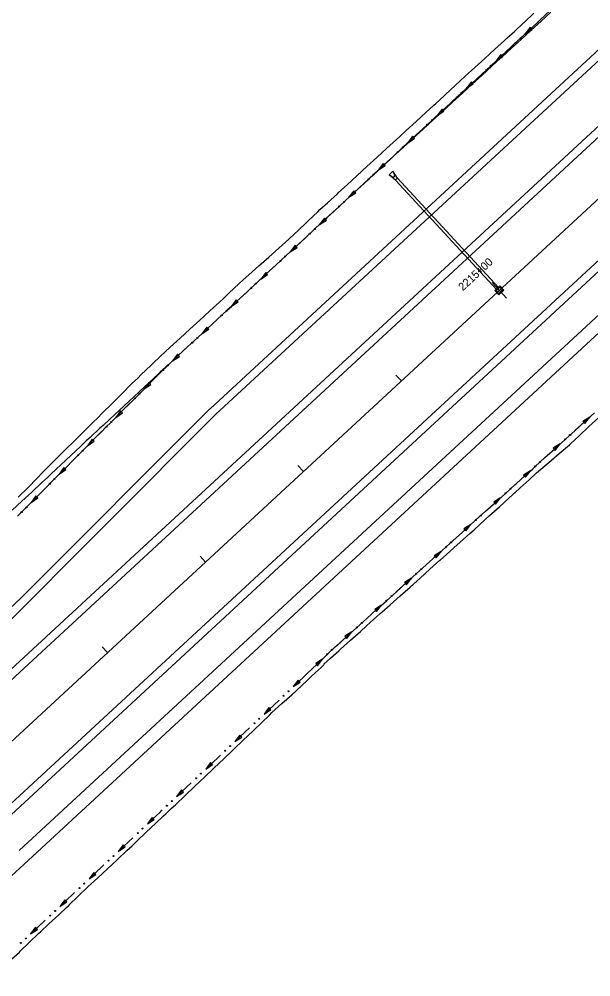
# Model space of a CAD drawing. Extents: x 1611108 to 1749517, y 619561 to 797725.
# Drawn here: x 1726166 to 1726595, y 770332 to 771050 of the extents above; entities that cross this region are included whole.
import ezdxf

# ---------------------------------------------------------------- set-up
doc = ezdxf.new("R2010")
doc.units = 0
for name, color, linetype in [('R_Ditch', 7, 'Continuous'), ('R_Drainage', 7, 'Continuous'), ('R_Horz Alg', 7, 'Continuous'), ('R_Horz Alg Stationing', 7, 'Continuous'), ('R_Proposed Const Limits', 7, 'Continuous'), ('R_Proposed Road', 7, 'Continuous')]:
    doc.layers.add(name, color=color, linetype=linetype)

msp = doc.modelspace()

# ---------------------------------------------------------------- linework, layer by layer
at = {"layer": 'R_Ditch'}
for p, q in [((1726549.3, 771043.7), (1726545.62, 771038.85)), ((1726545.62, 771038.85), (1726550.74, 771042.15)), ((1726550.74, 771042.15), (1726549.3, 771043.7)), ((1726527.27, 771023.28), (1726523.59, 771018.42)), ((1726523.59, 771018.42), (1726528.71, 771021.73)), ((1726528.71, 771021.73), (1726527.27, 771023.28)), ((1726505.24, 771002.85), (1726501.56, 770998)), ((1726501.56, 770998), (1726506.68, 771001.3)), ((1726506.68, 771001.3), (1726505.24, 771002.85)), ((1726483.22, 770982.43), (1726479.54, 770977.58)), ((1726484.65, 770980.88), (1726483.22, 770982.43)), ((1726479.54, 770977.58), (1726484.65, 770980.88)), ((1726461.19, 770962.01), (1726457.51, 770957.15)), ((1726462.63, 770960.46), (1726461.19, 770962.01)), ((1726457.51, 770957.15), (1726462.63, 770960.46)), ((1726439.16, 770941.59), (1726435.48, 770936.73)), ((1726435.48, 770936.73), (1726440.6, 770940.03)), ((1726440.6, 770940.03), (1726439.16, 770941.59)), ((1726417.13, 770921.16), (1726413.45, 770916.31)), ((1726413.45, 770916.31), (1726418.57, 770919.61)), ((1726418.57, 770919.61), (1726417.13, 770921.16)), ((1726395.11, 770900.74), (1726391.43, 770895.89)), ((1726391.43, 770895.89), (1726396.55, 770899.19)), ((1726396.55, 770899.19), (1726395.11, 770900.74)), ((1726373.08, 770880.32), (1726369.4, 770875.46)), ((1726369.4, 770875.46), (1726374.52, 770878.77)), ((1726374.52, 770878.77), (1726373.08, 770880.32)), ((1726351.05, 770859.89), (1726347.37, 770855.04)), ((1726347.37, 770855.04), (1726352.49, 770858.34)), ((1726352.49, 770858.34), (1726351.05, 770859.89)), ((1726329.03, 770839.47), (1726325.35, 770834.62)), ((1726330.47, 770837.92), (1726329.03, 770839.47)), ((1726325.35, 770834.62), (1726330.47, 770837.92)), ((1726307, 770819.05), (1726303.32, 770814.19)), ((1726303.32, 770814.19), (1726308.44, 770817.5)), ((1726308.44, 770817.5), (1726307, 770819.05)), ((1726284.97, 770798.63), (1726281.3, 770793.76)), ((1726281.3, 770793.76), (1726286.41, 770797.08)), ((1726286.41, 770797.08), (1726284.97, 770798.63)), ((1726263.44, 770777.63), (1726259.95, 770772.64)), ((1726259.95, 770772.64), (1726264.94, 770776.13)), ((1726264.94, 770776.13), (1726263.44, 770777.63)), ((1726242.2, 770756.39), (1726238.7, 770751.4)), ((1726238.7, 770751.4), (1726243.69, 770754.9)), ((1726243.69, 770754.9), (1726242.2, 770756.39)), ((1726594.04, 770751.54), (1726588.88, 770748.3)), ((1726588.88, 770748.3), (1726590.3, 770746.73)), ((1726590.3, 770746.73), (1726594.04, 770751.54)), ((1726220.98, 770735.12), (1726217.51, 770730.12)), ((1726217.51, 770730.12), (1726222.49, 770733.63)), ((1726222.49, 770733.63), (1726220.98, 770735.12)), ((1726571.74, 770731.42), (1726566.58, 770728.18)), ((1726568, 770726.61), (1726571.74, 770731.42)), ((1726566.58, 770728.18), (1726568, 770726.61)), ((1726199.81, 770713.81), (1726196.33, 770708.81)), ((1726196.33, 770708.81), (1726201.31, 770712.32)), ((1726201.31, 770712.32), (1726199.81, 770713.81)), ((1726549.44, 770711.29), (1726544.28, 770708.06)), ((1726545.7, 770706.49), (1726549.44, 770711.29)), ((1726544.28, 770708.06), (1726545.7, 770706.49)), ((1726178.64, 770692.51), (1726175.16, 770687.51)), ((1726175.16, 770687.51), (1726180.14, 770691.02)), ((1726180.14, 770691.02), (1726178.64, 770692.51)), ((1726527.14, 770691.17), (1726521.98, 770687.93)), ((1726523.4, 770686.36), (1726527.14, 770691.17)), ((1726521.98, 770687.93), (1726523.4, 770686.36)), ((1726504.84, 770671.04), (1726499.68, 770667.81)), ((1726499.68, 770667.81), (1726501.1, 770666.24)), ((1726501.1, 770666.24), (1726504.84, 770671.04)), ((1726482.54, 770650.92), (1726477.38, 770647.69)), ((1726477.38, 770647.69), (1726478.8, 770646.12)), ((1726478.8, 770646.12), (1726482.54, 770650.92)), ((1726460.24, 770630.8), (1726455.08, 770627.56)), ((1726456.5, 770625.99), (1726460.24, 770630.8)), ((1726455.08, 770627.56), (1726456.5, 770625.99)), ((1726437.94, 770610.67), (1726432.78, 770607.44)), ((1726434.19, 770605.87), (1726437.94, 770610.67)), ((1726432.78, 770607.44), (1726434.19, 770605.87)), ((1726415.64, 770590.55), (1726410.48, 770587.31)), ((1726411.89, 770585.74), (1726415.64, 770590.55)), ((1726410.48, 770587.31), (1726411.89, 770585.74)), ((1726393.65, 770570.1), (1726388.54, 770566.79)), ((1726388.54, 770566.79), (1726389.98, 770565.24)), ((1726389.98, 770565.24), (1726393.65, 770570.1)), ((1726375.39, 770554.49), (1726371.75, 770549.6)), ((1726371.75, 770549.6), (1726376.84, 770552.95)), ((1726376.84, 770552.95), (1726375.39, 770554.49)), ((1726353.52, 770533.89), (1726349.88, 770529.01)), ((1726349.88, 770529.01), (1726354.97, 770532.35)), ((1726354.97, 770532.35), (1726353.52, 770533.89)), ((1726331.65, 770513.3), (1726328.01, 770508.42)), ((1726328.01, 770508.42), (1726333.1, 770511.76)), ((1726333.1, 770511.76), (1726331.65, 770513.3)), ((1726309.78, 770492.71), (1726306.14, 770487.83)), ((1726306.14, 770487.83), (1726311.23, 770491.17)), ((1726311.23, 770491.17), (1726309.78, 770492.71)), ((1726287.91, 770472.12), (1726284.27, 770467.24)), ((1726284.27, 770467.24), (1726289.36, 770470.58)), ((1726289.36, 770470.58), (1726287.91, 770472.12)), ((1726266.04, 770451.53), (1726262.4, 770446.65)), ((1726267.49, 770449.99), (1726266.04, 770451.53)), ((1726262.4, 770446.65), (1726267.49, 770449.99)), ((1726244.17, 770430.94), (1726240.53, 770426.06)), ((1726245.62, 770429.4), (1726244.17, 770430.94)), ((1726240.53, 770426.06), (1726245.62, 770429.4)), ((1726222.3, 770410.35), (1726218.66, 770405.47)), ((1726218.66, 770405.47), (1726223.75, 770408.81)), ((1726223.75, 770408.81), (1726222.3, 770410.35)), ((1726200.44, 770389.76), (1726196.79, 770384.88)), ((1726196.79, 770384.88), (1726201.88, 770388.22)), ((1726201.88, 770388.22), (1726200.44, 770389.76)), ((1726178.52, 770369.22), (1726174.86, 770364.35)), ((1726174.86, 770364.35), (1726179.97, 770367.67)), ((1726179.97, 770367.67), (1726178.52, 770369.22))]:
    msp.add_line(p, q, dxfattribs=at)
for points in [[(1726564.92, 771055.12), (1726557.54, 771048.38), (1726550.16, 771041.63), (1726549.66, 771041.16), (1726542.78, 771034.88), (1726537.26, 771029.83), (1726535.4, 771028.13), (1726528.02, 771021.38), (1726527.34, 771020.75), (1726520.65, 771014.62), (1726513.29, 771007.86), (1726505.92, 771001.1), (1726498.55, 770994.34), (1726491.18, 770987.58), (1726490.18, 770986.67), (1726483.81, 770980.82), (1726482.52, 770979.64), (1726476.44, 770974.06), (1726469.07, 770967.3), (1726461.7, 770960.54), (1726456.87, 770956.11), (1726454.33, 770953.78), (1726446.96, 770947.02), (1726439.59, 770940.26), (1726432.22, 770933.5), (1726424.85, 770926.74), (1726417.49, 770919.98), (1726410.99, 770914.03), (1726410.99, 770914.02), (1726410.12, 770913.22), (1726402.79, 770906.42), (1726397.11, 770901.15), (1726395.46, 770899.62), (1726388.12, 770892.82), (1726386.36, 770891.19), (1726380.79, 770886.02), (1726374.08, 770879.8), (1726373.46, 770879.22), (1726366.12, 770872.42), (1726358.79, 770865.62), (1726351.46, 770858.83), (1726344.12, 770852.03), (1726339.95, 770848.16), (1726336.79, 770845.23), (1726329.46, 770838.43), (1726325.31, 770834.59), (1726322.12, 770831.63), (1726314.91, 770824.94), (1726314.79, 770824.83), (1726307.46, 770818.03), (1726300.13, 770811.23), (1726292.79, 770804.43), (1726285.46, 770797.63), (1726278.13, 770790.83), (1726272.02, 770785.17), (1726270.79, 770784.04), (1726263.46, 770777.24), (1726260.77, 770774.75), (1726256.13, 770770.44), (1726248.79, 770763.64), (1726241.46, 770756.84), (1726234.13, 770750.04), (1726229.11, 770745.39), (1726229.1, 770745.38), (1726226.8, 770743.23), (1726219.5, 770736.41), (1726216.58, 770733.68), (1726212.19, 770729.58), (1726204.88, 770722.75), (1726197.58, 770715.92), (1726190.27, 770709.09), (1726188.37, 770707.32), (1726187.61, 770706.6), (1726182.96, 770702.27), (1726175.66, 770695.44), (1726168.35, 770688.61), (1726161.04, 770681.78)], [(1726165.1, 770677.4), (1726172.16, 770684.49), (1726179.21, 770691.59), (1726186.27, 770698.69), (1726190.75, 770703.2), (1726191.5, 770703.95), (1726193.33, 770705.79), (1726200.38, 770712.89), (1726207.44, 770719.99), (1726214.49, 770727.09), (1726218.73, 770731.35), (1726221.55, 770734.19), (1726228.6, 770741.29), (1726230.82, 770743.53), (1726230.83, 770743.53), (1726235.67, 770748.37), (1726241.48, 770754.18), (1726242.75, 770755.45), (1726249.83, 770762.52), (1726256.9, 770769.6), (1726261.39, 770774.08), (1726263.98, 770776.67), (1726271.06, 770783.75), (1726272.24, 770784.93), (1726278.14, 770790.82), (1726285.46, 770797.63), (1726292.79, 770804.43), (1726300.13, 770811.23), (1726307.46, 770818.03), (1726314.79, 770824.83), (1726314.91, 770824.94), (1726322.12, 770831.63), (1726325.31, 770834.59), (1726329.46, 770838.43), (1726336.79, 770845.23), (1726339.95, 770848.16), (1726344.12, 770852.03), (1726351.46, 770858.83), (1726358.79, 770865.62), (1726366.12, 770872.42), (1726373.46, 770879.22), (1726374.08, 770879.8), (1726380.79, 770886.02), (1726386.36, 770891.19), (1726388.12, 770892.82), (1726395.46, 770899.62), (1726397.11, 770901.15), (1726402.79, 770906.42), (1726410.12, 770913.22), (1726410.99, 770914.03), (1726417.45, 770920.02), (1726424.79, 770926.82), (1726432.12, 770933.61), (1726439.45, 770940.41), (1726439.71, 770940.65), (1726446.79, 770947.21), (1726454.12, 770954.01), (1726456.65, 770956.35), (1726461.45, 770960.81), (1726468.79, 770967.61), (1726476.12, 770974.41), (1726482.17, 770980.02), (1726483.45, 770981.21), (1726489.79, 770987.08), (1726490.79, 770988.01), (1726498.12, 770994.81), (1726505.45, 771001.6), (1726512.78, 771008.4), (1726520.12, 771015.2), (1726523.83, 771018.64), (1726527.45, 771022), (1726534.78, 771028.8), (1726536.63, 771030.51), (1726542.12, 771035.6), (1726548.95, 771041.93), (1726549.45, 771042.4), (1726556.78, 771049.2), (1726564.11, 771056)], [(1726556.62, 771049.04), (1726549.45, 771042.4), (1726548.95, 771041.93), (1726545.62, 771038.85)], [(1726556.64, 771049.07), (1726556.62, 771049.04)], [(1726534.59, 771028.62), (1726527.45, 771022), (1726523.83, 771018.64), (1726523.59, 771018.42)], [(1726534.62, 771028.65), (1726534.59, 771028.62)], [(1726512.56, 771008.2), (1726505.45, 771001.6), (1726501.56, 770998)], [(1726512.59, 771008.22), (1726512.56, 771008.2)], [(1726490.53, 770987.78), (1726489.79, 770987.08), (1726483.45, 770981.21), (1726482.17, 770980.02), (1726479.54, 770977.58)], [(1726490.56, 770987.8), (1726490.54, 770987.78)], [(1726468.51, 770967.35), (1726461.45, 770960.81), (1726457.51, 770957.15)], [(1726468.54, 770967.38), (1726468.51, 770967.35)], [(1726446.48, 770946.93), (1726439.71, 770940.65), (1726439.45, 770940.41), (1726435.48, 770936.73)], [(1726446.51, 770946.96), (1726446.48, 770946.93)], [(1726424.45, 770926.51), (1726417.45, 770920.02), (1726413.45, 770916.31)], [(1726424.48, 770926.53), (1726424.45, 770926.51)], [(1726402.43, 770906.08), (1726397.11, 770901.15), (1726395.46, 770899.62), (1726391.43, 770895.89)], [(1726402.45, 770906.11), (1726402.43, 770906.08)], [(1726380.4, 770885.66), (1726374.08, 770879.8), (1726373.46, 770879.22), (1726369.4, 770875.46)], [(1726380.43, 770885.69), (1726380.4, 770885.66)], [(1726358.37, 770865.24), (1726351.46, 770858.83), (1726347.37, 770855.04)], [(1726358.4, 770865.26), (1726358.37, 770865.24)], [(1726336.35, 770844.81), (1726329.46, 770838.43), (1726325.35, 770834.62)], [(1726336.37, 770844.84), (1726336.35, 770844.81)], [(1726314.32, 770824.39), (1726307.46, 770818.03), (1726303.32, 770814.19)], [(1726314.35, 770824.42), (1726314.32, 770824.39)], [(1726292.29, 770803.97), (1726285.46, 770797.63), (1726281.3, 770793.76)], [(1726292.32, 770803.99), (1726292.29, 770803.97)], [(1726270.56, 770783.24), (1726263.98, 770776.67), (1726261.39, 770774.08), (1726259.95, 770772.64)], [(1726270.58, 770783.27), (1726270.56, 770783.24)], [(1726249.31, 770762.01), (1726242.75, 770755.45), (1726241.48, 770754.18), (1726238.7, 770751.4)], [(1726249.34, 770762.04), (1726249.31, 770762.01)], [(1726382.67, 770559.88), (1726385.67, 770562.67), (1726389.99, 770566.7), (1726392.3, 770568.84), (1726397.06, 770573.78), (1726403.15, 770579.28), (1726404.48, 770580.48), (1726411.91, 770587.18), (1726419.33, 770593.88), (1726424.04, 770598.13), (1726426.76, 770600.58), (1726434.18, 770607.28), (1726435.42, 770608.4), (1726441.61, 770613.98), (1726449.03, 770620.68), (1726456.46, 770627.38), (1726463.88, 770634.08), (1726471.31, 770640.78), (1726478.73, 770647.48), (1726478.85, 770647.59), (1726486.16, 770654.18), (1726489.39, 770657.1), (1726493.58, 770660.88), (1726501.01, 770667.58), (1726504.21, 770670.47), (1726508.43, 770674.28), (1726515.85, 770680.98), (1726523.28, 770687.68), (1726530.7, 770694.38), (1726538.13, 770701.08), (1726538.76, 770701.65), (1726545.55, 770707.78), (1726551.2, 770712.87), (1726552.98, 770714.48), (1726560.4, 770721.18), (1726562.07, 770722.69), (1726567.83, 770727.88), (1726575.25, 770734.58), (1726576.14, 770735.38), (1726582.68, 770741.28), (1726590.1, 770747.98), (1726597.53, 770754.68)], [(1726582.91, 770741.49), (1726590.1, 770747.98), (1726594.04, 770751.54)], [(1726228.08, 770740.76), (1726221.55, 770734.19), (1726218.73, 770731.35), (1726217.51, 770730.12)], [(1726228.1, 770740.79), (1726228.08, 770740.76)], [(1726582.88, 770741.46), (1726582.91, 770741.49)], [(1726560.61, 770721.37), (1726562.07, 770722.69), (1726567.83, 770727.88), (1726571.74, 770731.42)], [(1726206.91, 770719.45), (1726200.38, 770712.89), (1726196.33, 770708.81)], [(1726206.93, 770719.48), (1726206.91, 770719.45)], [(1726560.58, 770721.34), (1726560.61, 770721.37)], [(1726538.31, 770701.24), (1726538.76, 770701.65), (1726545.55, 770707.78), (1726549.44, 770711.29)], [(1726185.73, 770698.15), (1726179.21, 770691.59), (1726175.16, 770687.51)], [(1726185.76, 770698.17), (1726185.73, 770698.15)], [(1726538.28, 770701.22), (1726538.31, 770701.24)], [(1726516.01, 770681.12), (1726523.28, 770687.68), (1726527.14, 770691.17)], [(1726515.98, 770681.09), (1726516.01, 770681.12)], [(1726493.71, 770661), (1726501.01, 770667.58), (1726504.21, 770670.47), (1726504.84, 770671.04)], [(1726493.68, 770660.97), (1726493.71, 770660.99)], [(1726471.4, 770640.87), (1726478.73, 770647.48), (1726478.85, 770647.59), (1726482.54, 770650.92)], [(1726471.38, 770640.85), (1726471.4, 770640.87)], [(1726449.1, 770620.75), (1726456.46, 770627.38), (1726460.24, 770630.8)], [(1726449.08, 770620.72), (1726449.1, 770620.75)], [(1726426.8, 770600.62), (1726434.18, 770607.28), (1726435.42, 770608.4), (1726437.94, 770610.67)], [(1726426.78, 770600.6), (1726426.8, 770600.62)], [(1726404.5, 770580.5), (1726411.91, 770587.18), (1726415.64, 770590.55)], [(1726404.47, 770580.47), (1726404.48, 770580.48), (1726404.5, 770580.5)], [(1726382.67, 770559.88), (1726385.67, 770562.67), (1726389.99, 770566.7), (1726392.3, 770568.84), (1726393.58, 770570.17)], [(1726382.67, 770559.88), (1726379.77, 770557.15), (1726375.39, 770553.03), (1726375.38, 770553.02), (1726371.75, 770549.6)], [(1726360.8, 770539.29), (1726353.55, 770532.46), (1726351.66, 770530.68), (1726350.89, 770529.96), (1726349.88, 770529.01)], [(1726360.83, 770539.32), (1726360.83, 770539.32), (1726360.8, 770539.29)], [(1726338.93, 770518.7), (1726331.7, 770511.9), (1726328.01, 770508.42)], [(1726338.96, 770518.73), (1726338.93, 770518.7)], [(1726317.06, 770498.11), (1726309.86, 770491.33), (1726306.14, 770487.83)], [(1726317.09, 770498.14), (1726317.06, 770498.11)], [(1726295.19, 770477.52), (1726295.18, 770477.51), (1726288.02, 770470.77), (1726284.27, 770467.24)], [(1726295.22, 770477.55), (1726295.19, 770477.52)], [(1726273.32, 770456.93), (1726271.93, 770455.62), (1726271.88, 770455.57), (1726266.17, 770450.2), (1726262.4, 770446.65)], [(1726273.35, 770456.96), (1726273.32, 770456.93)], [(1726251.45, 770436.34), (1726248.18, 770433.26), (1726244.33, 770429.64), (1726240.53, 770426.06)], [(1726251.48, 770436.37), (1726251.45, 770436.34)], [(1726229.58, 770415.75), (1726222.49, 770409.07), (1726218.66, 770405.47)], [(1726229.61, 770415.77), (1726229.58, 770415.75)], [(1726207.71, 770395.16), (1726201.06, 770388.89), (1726200.94, 770388.78), (1726200.64, 770388.5), (1726199.01, 770386.96), (1726196.79, 770384.88)], [(1726207.74, 770395.18), (1726207.71, 770395.16)], [(1726185.82, 770374.59), (1726179.63, 770368.8), (1726178.42, 770367.67), (1726174.86, 770364.35)], [(1726185.85, 770374.62), (1726185.83, 770374.6), (1726185.82, 770374.59)]]:
    msp.add_lwpolyline(points, dxfattribs=at)
for centre in [(1726541.97, 771035.42), (1726538.3, 771032.01), (1726516.27, 771011.59), (1726519.94, 771014.99), (1726494.24, 770991.16), (1726497.92, 770994.57), (1726472.22, 770970.74), (1726475.89, 770974.15), (1726453.86, 770953.72), (1726450.19, 770950.32), (1726431.83, 770933.3), (1726428.16, 770929.89), (1726409.81, 770912.88), (1726406.13, 770909.47), (1726384.11, 770889.05), (1726387.78, 770892.46), (1726362.08, 770868.63), (1726365.75, 770872.03), (1726340.05, 770848.2), (1726343.73, 770851.61), (1726318.03, 770827.78), (1726321.7, 770831.19), (1726299.67, 770810.76), (1726296, 770807.36), (1726277.68, 770790.31), (1726274.13, 770786.77), (1726256.43, 770769.08), (1726252.89, 770765.53), (1726235.19, 770747.84), (1726231.64, 770744.3), (1726579.16, 770738.15), (1726575.44, 770734.8), (1726214, 770726.54), (1726210.47, 770722.99), (1726556.85, 770718.03), (1726553.14, 770714.67), (1726192.83, 770705.24), (1726189.3, 770701.68), (1726534.55, 770697.9), (1726530.84, 770694.55), (1726171.65, 770683.94), (1726168.12, 770680.38), (1726508.53, 770674.43), (1726512.25, 770677.78), (1726486.23, 770654.3), (1726489.95, 770657.66), (1726467.65, 770637.53), (1726463.93, 770634.18), (1726445.35, 770617.41), (1726441.63, 770614.05), (1726423.05, 770597.29), (1726419.33, 770593.93), (1726397.03, 770573.8), (1726400.75, 770577.16), (1726368.13, 770546.14), (1726364.48, 770542.71), (1726346.26, 770525.55), (1726342.61, 770522.12), (1726320.74, 770501.53), (1726324.39, 770504.96), (1726298.87, 770480.94), (1726302.52, 770484.37), (1726277, 770460.35), (1726280.65, 770463.78), (1726255.13, 770439.76), (1726258.78, 770443.19), (1726236.91, 770422.6), (1726233.26, 770419.16), (1726215.04, 770402.01), (1726211.39, 770398.57), (1726193.16, 770381.42), (1726189.51, 770378), (1726171.22, 770360.91), (1726167.55, 770357.5)]:
    msp.add_circle(centre, 0.375, dxfattribs=at)
at = {"layer": 'R_Drainage'}
for p, q in [((1726446.45, 770935.79), (1726443.52, 770933.07)), ((1726448.41, 770929.26), (1726443.52, 770933.07)), ((1726443.52, 770933.07), (1726446.07, 770931.62)), ((1726449.87, 770930.61), (1726446.45, 770935.79)), ((1726446.45, 770935.79), (1726447.7, 770933.13)), ((1726449.87, 770930.61), (1726448.41, 770929.26)), ((1726524.43, 770847.01), (1726448.41, 770929.26)), ((1726525.9, 770848.37), (1726449.87, 770930.61))]:
    msp.add_line(p, q, dxfattribs=at)
for points in [[(1726529.61, 770846.81), (1726526.67, 770849.99), (1726522.75, 770846.37), (1726525.7, 770843.19)], [(1726528.67, 770846.85), (1726526.63, 770849.05), (1726523.7, 770846.33), (1726525.73, 770844.13)]]:
    msp.add_lwpolyline(points, close=True, dxfattribs=at)
msp.add_arc((1726446.65, 770932.63), 1.17, 240.27992, 25.22008, dxfattribs=at)
at = {"layer": 'R_Horz Alg'}
msp.add_line((1726122.78, 770473.69), (1737235.67, 780746.34), dxfattribs=at)
at = {"layer": 'R_Horz Alg Stationing'}
for points in [[(1726520.75, 770852.46), (1726531.61, 770840.71)], [(1726448.68, 770783.12), (1726452.75, 770778.71)], [(1726375.25, 770715.24), (1726379.32, 770710.83)], [(1726301.81, 770647.36), (1726305.89, 770642.95)], [(1726228.38, 770579.47), (1726232.45, 770575.07)]]:
    msp.add_lwpolyline(points, dxfattribs=at)
at = {"layer": 'R_Proposed Const Limits'}
for points in [[(1726165.57, 770691.62), (1726172.71, 770698.63), (1726179.61, 770705.89), (1726184.1, 770710.4), (1726184.84, 770711.15), (1726186.68, 770712.98), (1726193.75, 770720.06), (1726200.84, 770727.12), (1726207.97, 770734.14), (1726212.25, 770738.36), (1726215.1, 770741.17), (1726222.24, 770748.17), (1726224.49, 770750.38), (1726224.49, 770750.39), (1726229.33, 770755.23), (1726235.14, 770761.04), (1726236.41, 770762.31), (1726243.48, 770769.39), (1726250.56, 770776.46), (1726255.11, 770780.87), (1726257.75, 770783.42), (1726264.94, 770790.37), (1726266.13, 770791.53), (1726272.12, 770797.33), (1726279.54, 770804.03), (1726286.93, 770810.78), (1726294.3, 770817.53), (1726301.65, 770824.32), (1726309.02, 770831.08), (1726309.14, 770831.18), (1726316.39, 770837.84), (1726319.59, 770840.78), (1726323.72, 770844.63), (1726331.03, 770851.46), (1726334.18, 770854.41), (1726338.38, 770858.24), (1726345.88, 770864.86), (1726353.38, 770871.47), (1726360.88, 770878.09), (1726368.29, 770884.81), (1726368.9, 770885.4), (1726375.53, 770891.71), (1726381.03, 770896.96), (1726382.77, 770898.61), (1726390.01, 770905.52), (1726391.64, 770907.06), (1726397.37, 770912.28), (1726404.78, 770919), (1726405.66, 770919.8), (1726412.17, 770925.73), (1726419.5, 770932.53), (1726426.87, 770939.3), (1726434.25, 770946.05), (1726434.5, 770946.28), (1726441.64, 770952.78), (1726449.04, 770959.51), (1726451.57, 770961.85), (1726456.38, 770966.3), (1726463.74, 770973.06), (1726471.11, 770979.82), (1726477.19, 770985.4), (1726478.48, 770986.59), (1726484.81, 770992.47), (1726485.81, 770993.39), (1726493.14, 771000.19), (1726500.47, 771006.99), (1726507.88, 771013.71), (1726515.28, 771020.43), (1726519.03, 771023.84), (1726522.67, 771027.17), (1726530.06, 771033.91), (1726531.92, 771035.61), (1726537.44, 771040.66), (1726544.3, 771046.96), (1726544.8, 771047.43), (1726552.17, 771054.19)], [(1726158.86, 770343.91), (1726166.45, 770350.67), (1726167.35, 770351.47), (1726173.78, 770357.69), (1726181.07, 770364.78), (1726182.27, 770365.92), (1726188.49, 770371.72), (1726195.92, 770378.63), (1726201.72, 770384.03), (1726203.35, 770385.56), (1726203.66, 770385.84), (1726203.78, 770385.95), (1726210.58, 770392.49), (1726217.75, 770399.46), (1726225.13, 770406.21), (1726232.48, 770412.99), (1726239.75, 770419.86), (1726247.01, 770426.73), (1726250.85, 770430.36), (1726254.28, 770433.61), (1726261.54, 770440.48), (1726268.8, 770447.36), (1726274.49, 770452.74), (1726274.55, 770452.79), (1726276.07, 770454.23), (1726280.3, 770458.24), (1726283.32, 770461.11), (1726290.58, 770467.99), (1726297.71, 770474.78), (1726297.83, 770474.89), (1726305.1, 770481.75), (1726312.38, 770488.6), (1726319.66, 770495.46), (1726326.82, 770502.45), (1726334.08, 770509.33), (1726341.35, 770516.2), (1726348.61, 770523.07), (1726353.23, 770527.44), (1726353.96, 770528.2), (1726355.74, 770530.1), (1726363.07, 770536.89), (1726370.66, 770543.41), (1726377.93, 770550.27), (1726377.94, 770550.28), (1726382.31, 770554.4), (1726385.2, 770557.15), (1726388.19, 770559.94), (1726392.53, 770563.95), (1726394.84, 770566.09), (1726394.53, 770566.45), (1726399.63, 770571), (1726405.76, 770576.47), (1726407.09, 770577.66), (1726414.53, 770584.35), (1726422, 770591), (1726426.73, 770595.22), (1726429.43, 770597.69), (1726436.87, 770604.37), (1726438.11, 770605.48), (1726444.37, 770611), (1726451.87, 770617.61), (1726459.38, 770624.22), (1726466.76, 770630.97), (1726474.14, 770637.72), (1726481.71, 770644.26), (1726481.83, 770644.37), (1726489.15, 770650.95), (1726492.38, 770653.85), (1726496.58, 770657.63), (1726504.04, 770664.3), (1726507.26, 770667.16), (1726511.47, 770670.99), (1726518.84, 770677.75), (1726526.28, 770684.43), (1726533.67, 770691.17), (1726541.06, 770697.91), (1726541.69, 770698.49), (1726548.45, 770704.65), (1726554.11, 770709.72), (1726555.92, 770711.29), (1726563.49, 770717.84), (1726565.19, 770719.31), (1726571.07, 770724.37), (1726578.69, 770730.86), (1726579.57, 770731.66), (1726586.04, 770737.64), (1726593.38, 770744.44), (1726600.76, 770751.18)]]:
    msp.add_lwpolyline(points, dxfattribs=at)
at = {"layer": 'R_Proposed Road'}
for p, q in [((1726095.63, 770503.06), (1728041.11, 772301.44)), ((1726099.71, 770498.66), (1728045.18, 772297.04)), ((1726145.86, 770448.72), (1728091.34, 772247.1)), ((1726149.94, 770444.32), (1728095.41, 772242.7)), ((1726309.35, 770757.81), (1726778.01, 771191.04)), ((1726313.42, 770753.41), (1726782.08, 771186.64)), ((1726173.02, 770419.35), (1726759.35, 770961.35)), ((1726166.23, 770426.69), (1726662.16, 770885.13)), ((1726101.27, 770540.96), (1726313.42, 770753.41)), ((1726167.82, 770616.1), (1726309.17, 770757.65)), ((1726072.55, 770528.03), (1726167.82, 770616.1))]:
    msp.add_line(p, q, dxfattribs=at)
msp.add_arc((1720937.13, 776083.5), 7713.44, 292.5, 312.75, dxfattribs=at)

# ---------------------------------------------------------------- texts
at = {"layer": 'R_Horz Alg Stationing'}
msp.add_text('2215+00', height=6, rotation=42.75, dxfattribs=at).set_placement((1726498.81, 770845.79))

doc.saveas('drawing.dxf')
